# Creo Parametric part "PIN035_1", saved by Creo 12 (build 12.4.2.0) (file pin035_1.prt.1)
Units: Custom; MM, KILOGRAM, SECS

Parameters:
  PTC_WM_ITERATION = "0"
  PTC_WM_VERSION = "-.0"
  PTC_WM_LIFECYCLE_STATE = "In Work"
  PTC_WM_LIFECYCLE = "MO_CADDocument"
  PTC_WM_CREATED_BY = "Maximilian Roepper (Z0017RMS: MO)"
  PTC_WM_CREATED_ON = "18-Sep-26 11:36:42 AM"
  PTC_WM_MODIFIED_BY = "Maximilian Roepper (Z0017RMS: MO)"
  PTC_WM_MODIFIED_ON = "18-Sep-26 11:36:46 AM"
  PDMLINKNUMBER = "PDM000071454811"
  PTC_WM_NAME = "pin035_1.prt"
  PTC_WM_NUMBER = "PDM000071454811"

Other parameters: WEIGHT, WEIGHT_FACTOR, WEIGHT_ADD, _MASS_TEMP, _DIFF_TEMP, MC_ERRORS, SUPPLIER

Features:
  1. coordinate system
  2. datum plane "PRT_YZ"
  3. datum plane "PRT_XY"
  4. datum plane "PRT_XZ"
  5. coordinate system
  6. datum axis
  7. datum axis
  8. datum axis
  9. coordinate system
  10. imported feature

Other named items: PRT, SIEMENS_MO, DRW_VIEW_ORG, PRT_X, PRT_Y, PRT_Z, CS0, ROUGH_GROB

Layers: 00_STD_CSYS-KSYS, 01_STD_PLANES-EBENEN, 02_STD_AXES-ACHSEN, 03_STD_CSYS-KSYS, 24_IMPORT_FEAT-IMPORT_KE

Surfaces: 10 plane, 4 cylinder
